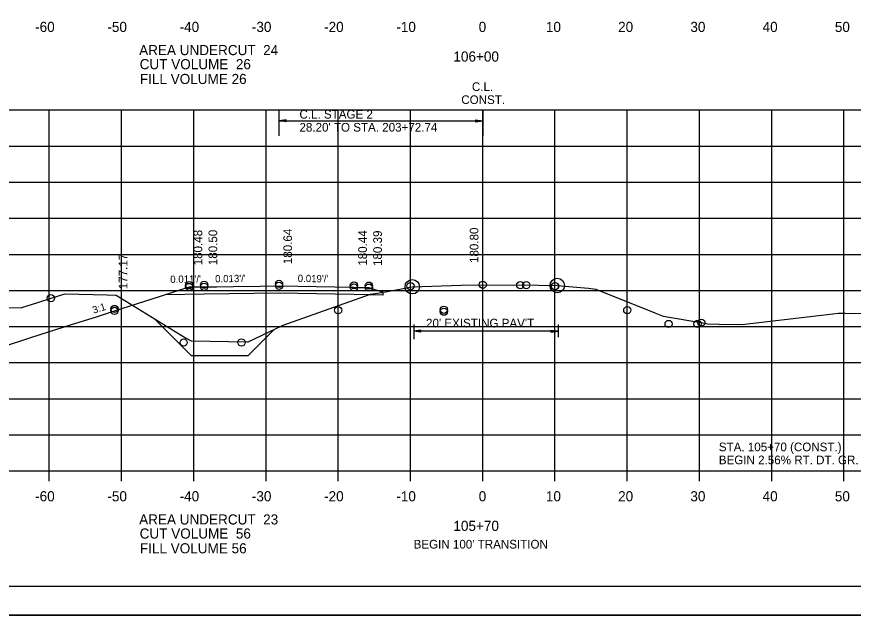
# Model space of a CAD drawing. Extents: x 1372132 to 1372465, y 380083 to 381790.
# Drawn here: x 1372237.5 to 1372353.3, y 380510.2 to 380593.1 of the extents above; entities that cross this region are included whole.
import ezdxf

# ---------------------------------------------------------------- set-up
doc = ezdxf.new("R2010")
doc.units = 0
for name, color, linetype in [('R_Alt Surface', 7, 'Continuous'), ('R_Axis', 7, 'Continuous'), ('R_Axis Annot', 7, 'Continuous'), ('R_Border', 7, 'Continuous'), ('R_Draft', 7, 'Continuous'), ('R_Erosion', 7, 'Continuous'), ('R_Exist Surface', 7, 'Continuous'), ('R_Fin Surface', 7, 'Continuous'), ('R_Grid', 7, 'Continuous'), ('R_No Plot', 7, 'Continuous'), ('R_Xsect Elev', 7, 'Continuous'), ('R_Xsect Slope', 7, 'Continuous')]:
    doc.layers.add(name, color=color, linetype=linetype)

msp = doc.modelspace()

# ---------------------------------------------------------------- linework, layer by layer
at = {"layer": 'R_Alt Surface'}
msp.add_lwpolyline([(1372288.23, 380554.51), (1372284.18, 380554.58), (1372273.81, 380554.79), (1372263.45, 380554.65), (1372258.03, 380554.56)], dxfattribs=at)
at = {"layer": 'R_Axis'}
for p, q in [((1372162.01, 380530.15), (1372442.01, 380530.15)), ((1372242.01, 380528.75), (1372242.01, 380530.15)), ((1372252.01, 380528.75), (1372252.01, 380530.15)), ((1372262.01, 380528.75), (1372262.01, 380530.15)), ((1372272.01, 380528.75), (1372272.01, 380530.15)), ((1372282.01, 380528.75), (1372282.01, 380530.15)), ((1372292.01, 380528.75), (1372292.01, 380530.15)), ((1372302.01, 380528.75), (1372302.01, 380530.15)), ((1372312.01, 380528.75), (1372312.01, 380530.15)), ((1372322.01, 380528.75), (1372322.01, 380530.15)), ((1372332.01, 380528.75), (1372332.01, 380530.15)), ((1372342.01, 380528.75), (1372342.01, 380530.15)), ((1372352.01, 380528.75), (1372352.01, 380530.15))]:
    msp.add_line(p, q, dxfattribs=at)
at = {"layer": 'R_Border'}
msp.add_line((1372460.19, 380514.15), (1372144.01, 380514.15), dxfattribs=at)
at = {"layer": 'R_Draft'}
for p, q in [((1372273.81, 380576.55), (1372273.81, 380580.15)), ((1372302.01, 380580.15), (1372302.01, 380576.55)), ((1372274.81, 380578.79), (1372273.81, 380578.64)), ((1372274.81, 380578.79), (1372273.81, 380578.64)), ((1372274.81, 380578.76), (1372273.98, 380578.64)), ((1372274.81, 380578.76), (1372273.98, 380578.64)), ((1372274.81, 380578.74), (1372274.15, 380578.64)), ((1372274.81, 380578.74), (1372274.15, 380578.64)), ((1372274.81, 380578.71), (1372274.32, 380578.64)), ((1372274.81, 380578.71), (1372274.32, 380578.64)), ((1372274.81, 380578.69), (1372274.49, 380578.64)), ((1372274.81, 380578.69), (1372274.49, 380578.64)), ((1372274.81, 380578.66), (1372274.65, 380578.64)), ((1372274.81, 380578.66), (1372274.65, 380578.64)), ((1372274.81, 380578.49), (1372274.81, 380578.79)), ((1372274.81, 380578.49), (1372274.81, 380578.79)), ((1372301.01, 380578.79), (1372302.01, 380578.64)), ((1372301.01, 380578.79), (1372301.01, 380578.49)), ((1372301.01, 380578.79), (1372302.01, 380578.64)), ((1372301.01, 380578.79), (1372301.01, 380578.49)), ((1372301.01, 380578.76), (1372301.85, 380578.64)), ((1372301.01, 380578.76), (1372301.85, 380578.64)), ((1372301.01, 380578.74), (1372301.68, 380578.64)), ((1372301.01, 380578.74), (1372301.68, 380578.64)), ((1372301.01, 380578.71), (1372301.51, 380578.64)), ((1372301.01, 380578.71), (1372301.51, 380578.64)), ((1372301.01, 380578.69), (1372301.34, 380578.64)), ((1372301.01, 380578.69), (1372301.34, 380578.64)), ((1372301.01, 380578.66), (1372301.17, 380578.64)), ((1372301.01, 380578.66), (1372301.17, 380578.64)), ((1372273.81, 380578.64), (1372302.01, 380578.64)), ((1372274.81, 380578.49), (1372273.81, 380578.64)), ((1372274.81, 380578.49), (1372273.81, 380578.64)), ((1372274.81, 380578.51), (1372273.98, 380578.64)), ((1372274.81, 380578.51), (1372273.98, 380578.64)), ((1372274.81, 380578.54), (1372274.15, 380578.64)), ((1372274.81, 380578.54), (1372274.15, 380578.64)), ((1372274.81, 380578.56), (1372274.32, 380578.64)), ((1372274.81, 380578.56), (1372274.32, 380578.64)), ((1372274.81, 380578.59), (1372274.49, 380578.64)), ((1372274.81, 380578.59), (1372274.49, 380578.64)), ((1372274.81, 380578.61), (1372274.65, 380578.64)), ((1372274.81, 380578.61), (1372274.65, 380578.64)), ((1372301.01, 380578.49), (1372302.01, 380578.64)), ((1372301.01, 380578.59), (1372301.34, 380578.64)), ((1372301.01, 380578.54), (1372301.68, 380578.64)), ((1372301.01, 380578.51), (1372301.85, 380578.64)), ((1372301.01, 380578.56), (1372301.51, 380578.64)), ((1372301.01, 380578.61), (1372301.17, 380578.64)), ((1372301.01, 380578.49), (1372302.01, 380578.64)), ((1372301.01, 380578.59), (1372301.34, 380578.64)), ((1372301.01, 380578.54), (1372301.68, 380578.64)), ((1372301.01, 380578.51), (1372301.85, 380578.64)), ((1372301.01, 380578.56), (1372301.51, 380578.64)), ((1372301.01, 380578.61), (1372301.17, 380578.64)), ((1372288.23, 380554.51), (1372288.23, 380554.92)), ((1372292.46, 380550.43), (1372292.46, 380548.42)), ((1372312.44, 380550.43), (1372312.44, 380548.66)), ((1372293.46, 380549.66), (1372292.46, 380549.51)), ((1372293.46, 380549.66), (1372292.46, 380549.51)), ((1372312.44, 380549.51), (1372292.46, 380549.51)), ((1372293.46, 380549.36), (1372292.46, 380549.51)), ((1372293.46, 380549.36), (1372292.46, 380549.51)), ((1372292.46, 380548.66), (1372292.46, 380548.66)), ((1372293.46, 380549.64), (1372292.62, 380549.51)), ((1372293.46, 380549.64), (1372292.62, 380549.51)), ((1372293.46, 380549.39), (1372292.62, 380549.51)), ((1372293.46, 380549.39), (1372292.62, 380549.51)), ((1372293.46, 380549.61), (1372292.8, 380549.51)), ((1372293.46, 380549.61), (1372292.8, 380549.51)), ((1372293.46, 380549.41), (1372292.8, 380549.51)), ((1372293.46, 380549.41), (1372292.8, 380549.51)), ((1372293.46, 380549.59), (1372292.96, 380549.51)), ((1372293.46, 380549.59), (1372292.96, 380549.51)), ((1372293.46, 380549.44), (1372292.96, 380549.51)), ((1372293.46, 380549.44), (1372292.96, 380549.51)), ((1372293.46, 380549.56), (1372293.13, 380549.51)), ((1372293.46, 380549.56), (1372293.13, 380549.51)), ((1372293.46, 380549.47), (1372293.13, 380549.51)), ((1372293.46, 380549.47), (1372293.13, 380549.51)), ((1372293.46, 380549.54), (1372293.3, 380549.51)), ((1372293.46, 380549.54), (1372293.3, 380549.51)), ((1372293.46, 380549.49), (1372293.3, 380549.51)), ((1372293.46, 380549.49), (1372293.3, 380549.51)), ((1372293.46, 380549.36), (1372293.46, 380549.66)), ((1372293.46, 380549.36), (1372293.46, 380549.66)), ((1372311.44, 380549.66), (1372312.44, 380549.51)), ((1372311.44, 380549.66), (1372311.44, 380549.36)), ((1372311.44, 380549.64), (1372312.27, 380549.51)), ((1372311.44, 380549.61), (1372312.1, 380549.51)), ((1372311.44, 380549.59), (1372311.93, 380549.51)), ((1372311.44, 380549.56), (1372311.76, 380549.51)), ((1372311.44, 380549.54), (1372311.6, 380549.51)), ((1372311.44, 380549.36), (1372312.44, 380549.51)), ((1372311.44, 380549.46), (1372311.76, 380549.51)), ((1372311.44, 380549.41), (1372312.1, 380549.51)), ((1372311.44, 380549.39), (1372312.27, 380549.51)), ((1372311.44, 380549.44), (1372311.93, 380549.51)), ((1372311.44, 380549.49), (1372311.6, 380549.51))]:
    msp.add_line(p, q, dxfattribs=at)
at = {"layer": 'R_Erosion'}
for p, q in [((1372261.63, 380546.16), (1372256.52, 380551.27)), ((1372269.56, 380546.16), (1372273.15, 380549.75)), ((1372261.63, 380546.16), (1372269.56, 380546.16))]:
    msp.add_line(p, q, dxfattribs=at)
at = {"layer": 'R_Exist Surface'}
msp.add_lwpolyline([(1372231.2, 380552.76), (1372238.23, 380552.8), (1372239.67, 380553.23), (1372244.15, 380554.7), (1372250.02, 380554.56), (1372251.28, 380554.5), (1372260.86, 380548.6), (1372261.64, 380548.16), (1372269.4, 380548.02), (1372269.56, 380548.02), (1372274.31, 380550.31), (1372274.39, 380550.34), (1372275.02, 380550.56), (1372286.45, 380554.65), (1372288.03, 380554.88), (1372292.25, 380555.66), (1372299.03, 380555.87), (1372301.92, 380555.95), (1372309.74, 380555.86), (1372312.32, 380555.83), (1372316.67, 380555.45), (1372317.66, 380555.35), (1372325.85, 380552.05), (1372326.97, 380551.59), (1372332.77, 380550.6), (1372333.14, 380550.53), (1372334.74, 380550.5), (1372337.88, 380550.45), (1372348.91, 380551.75), (1372351.25, 380552), (1372352.16, 380552), (1372356.1, 380551.96)], dxfattribs=at)
at = {"layer": 'R_Fin Surface'}
msp.add_lwpolyline([(1372235.25, 380547.26), (1372239.6, 380548.66), (1372245.09, 380550.42), (1372248.54, 380551.52), (1372251.03, 380552.32), (1372257.28, 380554.32), (1372261.38, 380555.63), (1372261.74, 380555.63), (1372263.45, 380555.65), (1372264.05, 380555.66), (1372265.16, 380555.67), (1372267.53, 380555.7), (1372271.21, 380555.75), (1372273.81, 380555.79), (1372284.13, 380555.59), (1372284.18, 380555.58), (1372284.19, 380555.58), (1372286.25, 380555.54), (1372288.22, 380554.91)], dxfattribs=at)
at = {"layer": 'R_Grid'}
for p, q in [((1372162.01, 380580.15), (1372442.01, 380580.15)), ((1372242.01, 380530.15), (1372242.01, 380580.15)), ((1372252.01, 380530.15), (1372252.01, 380580.15)), ((1372262.01, 380530.15), (1372262.01, 380580.15)), ((1372272.01, 380530.15), (1372272.01, 380580.15)), ((1372282.01, 380530.15), (1372282.01, 380580.15)), ((1372292.01, 380530.15), (1372292.01, 380580.15)), ((1372302.01, 380530.15), (1372302.01, 380580.15)), ((1372312.01, 380530.15), (1372312.01, 380580.15)), ((1372322.01, 380530.15), (1372322.01, 380580.15)), ((1372332.01, 380530.15), (1372332.01, 380580.15)), ((1372342.01, 380530.15), (1372342.01, 380580.15)), ((1372352.01, 380530.15), (1372352.01, 380580.15)), ((1372162.01, 380575.15), (1372442.01, 380575.15)), ((1372162.01, 380570.15), (1372442.01, 380570.15)), ((1372162.01, 380565.15), (1372442.01, 380565.15)), ((1372162.01, 380560.15), (1372442.01, 380560.15)), ((1372162.01, 380555.15), (1372442.01, 380555.15)), ((1372162.01, 380550.15), (1372442.01, 380550.15)), ((1372162.01, 380545.15), (1372442.01, 380545.15)), ((1372162.01, 380540.15), (1372442.01, 380540.15)), ((1372162.01, 380535.15), (1372442.01, 380535.15)), ((1372162.01, 380530.15), (1372442.01, 380530.15))]:
    msp.add_line(p, q, dxfattribs=at)
at = {"layer": 'R_No Plot'}
msp.add_line((1372131.61, 380510.17), (1372464.95, 380510.17), dxfattribs=at)
for points in [[(1372131.61, 380723.5), (1372464.95, 380723.5), (1372464.95, 380510.17), (1372131.61, 380510.17)], [(1372377.93, 380719.61), (1372377.93, 380709.73), (1372413.67, 380709.73), (1372413.67, 380706.81), (1372436.87, 380706.81), (1372436.87, 380682.48), (1372460.19, 380682.48), (1372460.19, 380514.15), (1372144.01, 380514.15), (1372144.01, 380719.61)]]:
    msp.add_lwpolyline(points, close=True, dxfattribs=at)
for centre, radius in [((1372292.25, 380555.66), 1), ((1372312.32, 380555.83), 1), ((1372261.38, 380555.9), 0.5), ((1372261.38, 380555.63), 0.5), ((1372263.45, 380555.93), 0.5), ((1372263.45, 380555.65), 0.5), ((1372273.81, 380556.06), 0.5), ((1372273.81, 380555.79), 0.5), ((1372284.18, 380555.86), 0.5), ((1372284.18, 380555.58), 0.5), ((1372286.25, 380555.82), 0.5), ((1372286.25, 380555.54), 0.5), ((1372292, 380555.75), 0.5), ((1372292.01, 380555.75), 0.5), ((1372302.01, 380555.95), 0.5), ((1372307.21, 380555.89), 0.5), ((1372308.03, 380555.88), 0.5), ((1372312.01, 380555.75), 0.5), ((1372312.02, 380555.75), 0.5), ((1372242.23, 380554.07), 0.5), ((1372251.03, 380552.59), 0.5), ((1372251.03, 380552.32), 0.5), ((1372282, 380552.41), 0.5), ((1372296.62, 380552.48), 0.5), ((1372296.62, 380552.21), 0.5), ((1372322.02, 380552.41), 0.5), ((1372327.74, 380550.51), 0.5), ((1372331.74, 380550.51), 0.5), ((1372332.27, 380550.69), 0.5), ((1372260.61, 380547.95), 0.5), ((1372268.61, 380547.95), 0.5)]:
    msp.add_circle(centre, radius, dxfattribs=at)
at = {"layer": 'R_Xsect Elev'}
msp.add_line((1372302.01, 380555.95), (1372302.01, 380565.95), dxfattribs=at)

# ---------------------------------------------------------------- texts
at = {"layer": 'R_Axis Annot'}
for s, p in [('-60', (1372240.05, 380590.95)), ('-50', (1372250.05, 380590.95)), ('-40', (1372260.05, 380590.95)), ('-30', (1372270.05, 380590.95)), ('-20', (1372280.05, 380590.95)), ('-10', (1372290.05, 380590.95)), ('0', (1372301.45, 380590.95)), ('10', (1372310.75, 380590.95)), ('20', (1372320.75, 380590.95)), ('30', (1372330.75, 380590.95)), ('40', (1372340.75, 380590.95)), ('50', (1372350.75, 380590.95)), ('AREA UNDERCUT  24', (1372254.45, 380587.74)), ('106+00', (1372297.95, 380586.85)), ('CUT VOLUME  26', (1372254.52, 380585.79)), ('FILL VOLUME 26', (1372254.55, 380583.74)), ('-60', (1372240.05, 380525.95)), ('-50', (1372250.05, 380525.95)), ('-40', (1372260.05, 380525.95)), ('-30', (1372270.05, 380525.95)), ('-20', (1372280.05, 380525.95)), ('-10', (1372290.05, 380525.95)), ('0', (1372301.45, 380525.95)), ('10', (1372310.75, 380525.95)), ('20', (1372320.75, 380525.95)), ('30', (1372330.75, 380525.95)), ('40', (1372340.75, 380525.95)), ('50', (1372350.75, 380525.95)), ('AREA UNDERCUT  23', (1372254.45, 380522.74)), ('105+70', (1372297.95, 380521.85)), ('CUT VOLUME  56', (1372254.52, 380520.79)), ('FILL VOLUME 56', (1372254.55, 380518.74))]:
    msp.add_text(s, height=1.4, dxfattribs=at).set_placement(p)
at = {"layer": 'R_Draft'}
for s, p in [('C.L. ', (1372300.51, 380582.77)), ('CONST. ', (1372299.04, 380580.97)), ('C.L. STAGE 2', (1372276.64, 380578.95)), ("28.20' TO STA. 203+72.74", (1372276.64, 380577.15)), ("20' EXISTING PAV'T", (1372294.16, 380550.03))]:
    msp.add_text(s, height=1.2, rotation=360, dxfattribs=at).set_placement(p)
for s, p in [('STA. 105+70 (CONST.)', (1372334.69, 380532.88)), ('BEGIN 2.56% RT. DT. GR.', (1372334.69, 380531.08)), ("BEGIN 100' TRANSITION", (1372292.44, 380519.41))]:
    msp.add_text(s, height=1.2, dxfattribs=at).set_placement(p)
at = {"layer": 'R_Xsect Elev'}
for s, p in [('180.64', (1372275.61, 380558.79)), ('180.80', (1372301.41, 380558.95)), ('180.48', (1372263.18, 380558.63)), ('180.50', (1372265.25, 380558.65)), ('180.44', (1372285.98, 380558.58)), ('180.39', (1372288.05, 380558.54)), ('177.17', (1372252.83, 380555.32))]:
    msp.add_text(s, height=1.2, rotation=90, dxfattribs=at).set_placement(p)
at = {"layer": 'R_Xsect Slope'}
for s, rotation, p in [("0.011'/'", 0.6095, (1372258.76, 380556.2)), ("0.013'/'", 0.7359, (1372264.97, 380556.27)), ("0.019'/'", 358.8875, (1372276.39, 380556.34)), ('3:1', 17.7524, (1372248.16, 380551.92))]:
    msp.add_text(s, height=1, rotation=rotation, dxfattribs=at).set_placement(p)

doc.saveas('drawing.dxf')
